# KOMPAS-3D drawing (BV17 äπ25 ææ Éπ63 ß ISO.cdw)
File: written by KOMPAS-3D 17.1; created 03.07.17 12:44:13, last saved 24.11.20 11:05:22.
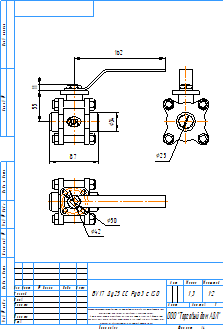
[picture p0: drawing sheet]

Sheet 1: A4, portrait

Title block, sheet 1: name: BV17 Ду25 СС Ру63 с ISO; material: Сталь 20  ГОСТ 1050-88; mass: 1,3; sheets: 1; sheet format: A4; stored path: C:\Users\kka\KOMPAS_Work\!Trash\СС02 СС03 ФФ Смотровые стекла\СС01.cdw

Views: Спереди 4, Проекционный вид 5, Проекционный вид 6
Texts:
  Klimkovich
  ADL
  Рама для чертежей
  Лит-Масса-Масштаб
  Материал-Предприятие
  Масштаб
  Изм.
  Лист
  № докум.
  Подп.
  Дата
  Лит.
  Разраб.
  Пров.
  Т.контр.
  Листов
  Внимание! Данный продукт является объектом авторского права ООО «Торговый Дом АДЛ».
  Запрещается изменение, копирование, распространение
  (в том числе путем копирования на другие сайты и ресурсы в Интернете)
  или любое иное использование информации и объектов без предварительного
  согласия правообладателя (ООО «Торговый Дом АДЛ»).
  Н.контр.
  Утв.
  ООО "Торговый дом АДЛ"
  Изменение
  Номер документа
  Подпись
  Обозначение документа
  Наименование изделия
  Масса изделия по ГОСТ 2.109-73
  Порядковый номер листа
  Общее количество листов в документе
  Характер работы, выполненной лицом, подписавшим документ
  Наименование или индекс предприятия, выпускающего документ
  Инв. № подл.
  Подп. и дата
  Взам. инв. №
  Инв. № дубл.
  Инвентарный номер подлинника по ГОСТ 2.501-68
  Подпись принявшего подлинник в отдел технической документации
  Инвентарный номер подлинника, взамен которого выпущен данный подлинник
  Инвентарный номер дубликата по ГОСТ 2.502-68
  Подпись принявшего дубликат в отдел технической документации
  Справ. №
  Перв. примен.
  Обозначение документа, взамен или на основании которого выпущен данный документ
  Обозначение документа, в котором впервые записан данный документ
  Подпись лица, копировавшего чертеж
  Обозначение формата листа
  !Рама для чертежа
Dimensions and other numbers on the sheet: 87; 55; 34; 11; 162; 50; 42; 25; 1:2; 1; 1,3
